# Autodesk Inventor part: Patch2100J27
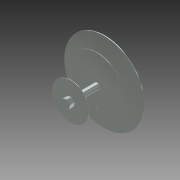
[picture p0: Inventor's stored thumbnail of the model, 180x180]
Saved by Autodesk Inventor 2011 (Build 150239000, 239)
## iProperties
Created: 2014-07
Part Number: Patch2100J27
Document SubType Name: Modeling
Designer: Evgeny
Density: 1 g/cm^3
Author: Evgeny
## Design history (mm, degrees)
sketch "Эскиз1"
  geometry: L1 (28.5, 24.372)-(28.5, -24.372); L2 (-28.5, -24.372)-(-28.5, 24.372); C1 r 1.35 at (0, -27); A1 r 37.5 centre (0, 0) between (28.5, 24.372) and (-28.5, 24.372); A2 r 37.5 centre (0, 0) between (-28.5, -24.372) and (28.5, -24.372); 1 further point
  constraints: 4 end point, 4 point on circle, 3 centre point, 1 coincident, 1 parallel
  dimensions: "d1" = 57 distance between parallel lines of L1 L2; "d2" = 28.5 distance from line of L2 point (0, 0); "d3" = 37.5 radius of A1; "d4" = 37.5 radius of A2; "d5" = 2.7 diameter of C1; "d6" = 27 distance of point (0, 0) C1.centre
extrude "Выдавливание1" new body sketch "Эскиз1" distance "d7" = 0.5; taper "d8" = 0 deg
sketch "Эскиз2"
  geometry: C1 r 4 at (0, 0); A1 r 37.5 centre (0, 0) between (-28.5, -24.372) and (28.5, -24.372) reference
  constraints: 1 centre point, 1 coincident
  dimensions: "d9" = 8 diameter of C1
extrude "Выдавливание2" join sketch "Эскиз2" distance "d10" = 8.9; taper "d11" = 0 deg; dims "d20" = 48
sketch "Эскиз3"
  geometry: C1 r 4 at (0, 0) reference; C2 r 52 at (0, 0); C3 r 4 at (0, -27)
  constraints: 2 centre point, 1 coincident
  dimensions: "d12" = 104 diameter of C2; "d13" = 8 diameter of C3; "d14" = 27 distance of C3.centre C1.centre
extrude "Выдавливание3" join sketch "Эскиз3" distance "d15" = 1; taper "d16" = 0 deg
sketch "Эскиз4"
  geometry: C1 r 4 at (0, 0); A1 r 37.5 centre (0, 0) between (-28.5, -24.372) and (28.5, -24.372) reference
  constraints: 1 centre point, 1 coincident
  dimensions: "d17" = 8 diameter of C1
extrude "Выдавливание4" join sketch "Эскиз4" distance "d18" = 34; taper "d19" = 0 deg
sketch "Эскиз5"
  geometry: C1 r 4 at (0, 0) reference; C2 r 24 at (0, 0)
  constraints: 1 centre point, 1 coincident
  dimensions: "d20" = 48 diameter of C2
extrude "Выдавливание5" join sketch "Эскиз5" distance "d21" = 0.5; taper "d22" = 0 deg
sketch "Эскиз6"
  geometry: L1 (-1.421, -5.596)-(-5.557, -1.567); L2 (-5.557, -1.567)-(-4.136, 4.029); L3 (-4.136, 4.029)-(1.421, 5.596); L4 (1.421, 5.596)-(5.557, 1.567); L5 (5.557, 1.567)-(4.136, -4.029); L6 (4.136, -4.029)-(-1.421, -5.596); C1 r 24 at (0, 0) reference; 1 further point
  constraints: 12 end point, 1 coincident, 13 other
  dimensions: "d24" = 10 distance between parallel lines of L6 L3
extrude "Выдавливание6" join sketch "Эскиз6" distance "d25" = 6; taper "d26" = 0 deg
sketch "Эскиз7"
  geometry: L1 (0, -5.774)-(-5, -2.887); L2 (-5, -2.887)-(-5, 2.887); L3 (-5, 2.887)-(0, 5.774); L4 (0, 5.774)-(5, 2.887); L5 (5, 2.887)-(5, -2.887); L6 (5, -2.887)-(0, -5.774); C1 r 52 at (0, 0) reference; 1 further point
  constraints: 12 end point, 1 coincident, 13 other
  dimensions: "d27" = 10 distance between parallel lines of L5 L2
extrude "Выдавливание7" join sketch "Эскиз7" distance "d28" = 6; taper "d29" = 0 deg
sketch "Эскиз8"
  geometry: C1 r 3 at (0, 0); 1 further point
  constraints: 1 centre point, 1 coincident
  dimensions: "d30" = 6 diameter of C1
extrude "Выдавливание8" join sketch "Эскиз8" distance "d31" = 6; taper "d32" = 0 deg
extrude "Выдавливание9" join sketch "Эскиз1" distance "d33" = 1; taper "d35" = 0 deg; dims "d34" = 9.9, "d36" = 0
node "Твердое тело1"
other parameters: "d0" = 75
